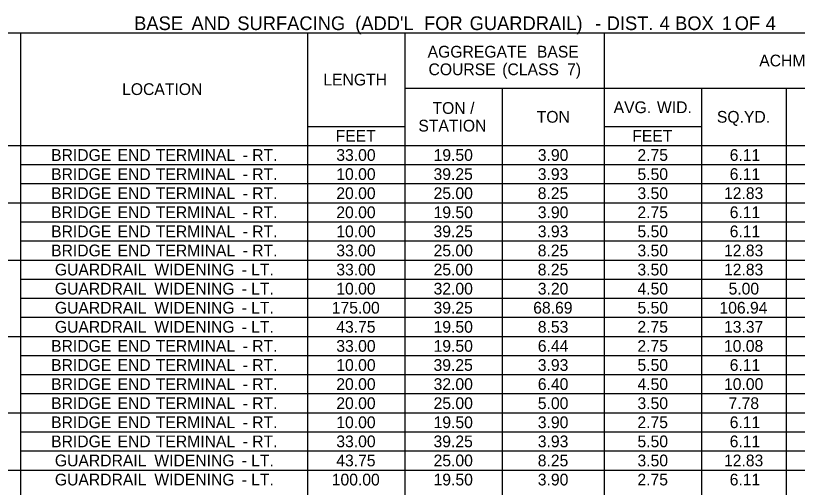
# Model space of a CAD drawing. Extents: x 540541 to 1930787, y -1948574 to 596640.
# Drawn here: x 556174.1 to 556573.6, y -1946479.8 to -1946238.9 of the extents above; entities that cross this region are included whole.
import ezdxf

# ---------------------------------------------------------------- set-up
doc = ezdxf.new("R2010")
doc.units = 0
doc.layers.add('Default', color=7, linetype='Continuous')

msp = doc.modelspace()

# ---------------------------------------------------------------- linework, layer by layer
at = {"layer": 'Default'}
for p, q in [((555955.32, -1946247.69), (556842.08, -1946247.69)), ((556176.64, -1946704.96), (556176.64, -1946247.69)), ((556323.38, -1946695.21), (556323.38, -1946247.69)), ((556373.11, -1946695.21), (556373.11, -1946247.69)), ((556474.99, -1946704.96), (556474.99, -1946247.69)), ((556373.11, -1946275.96), (556842.08, -1946275.96)), ((556422.83, -1946704.96), (556422.83, -1946275.96)), ((556524.72, -1946275.96), (556568.11, -1946275.96)), ((556524.72, -1946704.96), (556524.72, -1946275.96)), ((556568.11, -1946704.96), (556568.11, -1946275.96)), ((556323.38, -1946295.46), (556373.11, -1946295.46)), ((556373.11, -1946695.21), (556373.11, -1946295.46)), ((556474.99, -1946295.46), (556524.72, -1946295.46)), ((556474.99, -1946305.21), (556474.99, -1946295.46)), ((556524.72, -1946704.96), (556524.72, -1946295.46)), ((555955.32, -1946305.21), (556373.11, -1946305.21)), ((556373.11, -1946305.21), (556524.72, -1946305.21)), ((556422.83, -1946704.96), (556422.83, -1946305.21)), ((556524.72, -1946305.21), (556842.08, -1946305.21)), ((556568.11, -1946704.96), (556568.11, -1946305.21)), ((556176.64, -1946314.96), (556842.08, -1946314.96)), ((556323.38, -1946441.71), (556323.38, -1946314.96)), ((556176.64, -1946324.71), (556842.08, -1946324.71)), ((556126.92, -1946334.46), (556842.08, -1946334.46)), ((556176.64, -1946344.21), (556842.08, -1946344.21)), ((556176.64, -1946353.96), (556842.08, -1946353.96)), ((556126.92, -1946363.71), (556842.08, -1946363.71)), ((556176.64, -1946373.46), (556842.08, -1946373.46)), ((556176.64, -1946383.21), (556842.08, -1946383.21)), ((556176.64, -1946392.96), (556842.08, -1946392.96)), ((556126.92, -1946402.71), (556474.99, -1946402.71)), ((556422.83, -1946402.71), (556474.99, -1946402.71)), ((556474.99, -1946402.71), (556842.08, -1946402.71)), ((556176.64, -1946412.46), (556842.08, -1946412.46)), ((556176.64, -1946422.21), (556474.99, -1946422.21)), ((556422.83, -1946422.21), (556474.99, -1946422.21)), ((556474.99, -1946422.21), (556842.08, -1946422.21)), ((556176.64, -1946431.96), (556474.99, -1946431.96)), ((556422.83, -1946431.96), (556474.99, -1946431.96)), ((556474.99, -1946431.96), (556842.08, -1946431.96)), ((555955.32, -1946441.71), (556323.38, -1946441.71)), ((556126.92, -1946441.71), (556842.08, -1946441.71)), ((556176.64, -1946451.46), (556842.08, -1946451.46)), ((556323.38, -1946470.96), (556323.38, -1946451.46)), ((556176.64, -1946461.21), (556842.08, -1946461.21)), ((556126.92, -1946470.96), (556323.38, -1946470.96)), ((556176.64, -1946470.96), (556323.38, -1946470.96)), ((556323.38, -1946470.96), (556842.08, -1946470.96))]:
    msp.add_line(p, q, dxfattribs=at)

# ---------------------------------------------------------------- texts
for s, height, p in [('BASE', 7, (556234.63, -1946246.29)), (' AND', 7, (556261.33, -1946246.29)), (' SURFACING', 7, (556284.75, -1946246.29)), (" (ADD'L", 7, (556345.02, -1946246.29)), (' FOR', 7, (556380.19, -1946246.29)), (' GUARDRAIL)', 7, (556403.5, -1946246.29)), (' DIST.', 7, (556473.55, -1946246.29)), (' 4', 7, (556500.59, -1946246.29)), (' BOX', 7, (556508.52, -1946246.29)), (' 1', 7, (556532.42, -1946246.29)), (' OF', 7, (556538.99, -1946246.29)), (' 4', 7, (556554.84, -1946246.29)), (' -', 7, (556467.65, -1946246.29)), ('AGGREGATE', 6, (556384.64, -1946260.33)), (' BASE', 6, (556438.26, -1946260.33)), ('ACHM', 6, (556554.14, -1946264.83)), ('COURSE', 6, (556385.09, -1946269.33)), (' (CLASS', 6, (556420.54, -1946269.33)), (' 7)', 6, (556453.67, -1946269.33)), ('LENGTH', 6, (556331.33, -1946274.58)), ('LOCATION', 6, (556228.46, -1946279.45)), ('TON', 6, (556387.12, -1946289.09)), (' /', 6, (556404.15, -1946289.09)), ('AVG.', 6, (556479.71, -1946288.71)), (' WID.', 6, (556499.63, -1946288.71)), ('TON', 6, (556440.4, -1946293.59)), ('SQ.YD.', 6, (556532.49, -1946293.59)), ('STATION', 6, (556379.91, -1946298.09)), ('FEET', 6, (556337.61, -1946303.34)), ('FEET', 6, (556489.23, -1946303.34)), ('BRIDGE', 6, (556192.18, -1946313.09)), (' END', 6, (556223.88, -1946313.09)), (' TERMINAL', 6, (556243.46, -1946313.09)), (' RT.', 6, (556292.74, -1946313.09)), ('33.00', 6, (556337.96, -1946313.09)), ('19.50', 6, (556387.69, -1946313.09)), ('3.90', 6, (556440.96, -1946313.09)), ('2.75', 6, (556491.87, -1946313.09)), ('6.11', 6, (556539.03, -1946313.09)), (' -', 6, (556287.88, -1946313.09)), ('BRIDGE', 6, (556192.18, -1946322.84)), (' END', 6, (556223.88, -1946322.84)), (' TERMINAL', 6, (556243.46, -1946322.84)), (' RT.', 6, (556292.74, -1946322.84)), ('10.00', 6, (556337.96, -1946322.84)), ('39.25', 6, (556387.65, -1946322.84)), ('3.93', 6, (556440.95, -1946322.84)), ('5.50', 6, (556491.9, -1946322.84)), ('6.11', 6, (556539.03, -1946322.84)), (' -', 6, (556287.88, -1946322.84)), ('BRIDGE', 6, (556192.18, -1946332.59)), (' END', 6, (556223.88, -1946332.59)), (' TERMINAL', 6, (556243.46, -1946332.59)), (' RT.', 6, (556292.74, -1946332.59)), ('20.00', 6, (556337.96, -1946332.59)), ('25.00', 6, (556387.69, -1946332.59)), ('8.25', 6, (556440.92, -1946332.59)), ('3.50', 6, (556491.9, -1946332.59)), ('12.83', 6, (556536.12, -1946332.59)), (' -', 6, (556287.88, -1946332.59)), ('BRIDGE', 6, (556192.18, -1946342.34)), (' END', 6, (556223.88, -1946342.34)), (' TERMINAL', 6, (556243.46, -1946342.34)), (' RT.', 6, (556292.74, -1946342.34)), ('20.00', 6, (556337.96, -1946342.34)), ('19.50', 6, (556387.69, -1946342.34)), ('3.90', 6, (556440.96, -1946342.34)), ('2.75', 6, (556491.87, -1946342.34)), ('6.11', 6, (556539.03, -1946342.34)), (' -', 6, (556287.88, -1946342.34)), ('BRIDGE', 6, (556192.18, -1946352.09)), (' END', 6, (556223.88, -1946352.09)), (' TERMINAL', 6, (556243.46, -1946352.09)), (' -', 6, (556287.88, -1946352.09)), (' RT.', 6, (556292.74, -1946352.09)), ('10.00', 6, (556337.96, -1946352.09)), ('39.25', 6, (556387.65, -1946352.09)), ('3.93', 6, (556440.95, -1946352.09)), ('5.50', 6, (556491.9, -1946352.09)), ('6.11', 6, (556539.03, -1946352.09)), ('BRIDGE', 6, (556192.18, -1946361.84)), (' END', 6, (556223.88, -1946361.84)), (' TERMINAL', 6, (556243.46, -1946361.84)), (' RT.', 6, (556292.74, -1946361.84)), ('33.00', 6, (556337.96, -1946361.84)), ('25.00', 6, (556387.69, -1946361.84)), ('8.25', 6, (556440.92, -1946361.84)), ('3.50', 6, (556491.9, -1946361.84)), ('12.83', 6, (556536.12, -1946361.84)), (' -', 6, (556287.88, -1946361.84)), ('GUARDRAIL', 6, (556194.1, -1946371.59)), (' WIDENING', 6, (556242.72, -1946371.59)), ('33.00', 6, (556337.96, -1946371.59)), ('25.00', 6, (556387.69, -1946371.59)), ('8.25', 6, (556440.92, -1946371.59)), ('3.50', 6, (556491.9, -1946371.59)), ('12.83', 6, (556536.12, -1946371.59)), (' -', 6, (556287.36, -1946371.59)), (' LT.', 6, (556292.22, -1946371.59)), ('GUARDRAIL', 6, (556194.1, -1946381.34)), (' WIDENING', 6, (556242.72, -1946381.34)), (' LT.', 6, (556292.22, -1946381.34)), ('10.00', 6, (556337.96, -1946381.34)), ('32.00', 6, (556387.69, -1946381.34)), ('3.20', 6, (556440.96, -1946381.34)), ('4.50', 6, (556491.9, -1946381.34)), ('5.00', 6, (556538.46, -1946381.34)), (' -', 6, (556287.36, -1946381.34)), ('GUARDRAIL', 6, (556194.1, -1946391.09)), (' WIDENING', 6, (556242.72, -1946391.09)), (' LT.', 6, (556292.22, -1946391.09)), ('175.00', 6, (556335.63, -1946391.09)), ('39.25', 6, (556387.65, -1946391.09)), ('68.69', 6, (556438.61, -1946391.09)), ('5.50', 6, (556491.9, -1946391.09)), ('106.94', 6, (556533.8, -1946391.09)), (' -', 6, (556287.36, -1946391.09)), ('GUARDRAIL', 6, (556194.1, -1946400.84)), (' WIDENING', 6, (556242.72, -1946400.84)), (' LT.', 6, (556292.22, -1946400.84)), ('43.75', 6, (556337.93, -1946400.84)), ('19.50', 6, (556387.69, -1946400.84)), ('8.53', 6, (556440.95, -1946400.84)), ('2.75', 6, (556491.87, -1946400.84)), ('13.37', 6, (556536.12, -1946400.84)), (' -', 6, (556287.36, -1946400.84)), ('BRIDGE', 6, (556192.18, -1946410.59)), (' END', 6, (556223.88, -1946410.59)), (' TERMINAL', 6, (556243.46, -1946410.59)), (' RT.', 6, (556292.74, -1946410.59)), ('33.00', 6, (556337.96, -1946410.59)), ('19.50', 6, (556387.69, -1946410.59)), ('6.44', 6, (556440.96, -1946410.59)), ('2.75', 6, (556491.87, -1946410.59)), ('10.08', 6, (556536.11, -1946410.59)), (' -', 6, (556287.88, -1946410.59)), ('BRIDGE', 6, (556192.18, -1946420.34)), (' END', 6, (556223.88, -1946420.34)), (' TERMINAL', 6, (556243.46, -1946420.34)), (' RT.', 6, (556292.74, -1946420.34)), ('10.00', 6, (556337.96, -1946420.34)), ('39.25', 6, (556387.65, -1946420.34)), ('3.93', 6, (556440.95, -1946420.34)), ('5.50', 6, (556491.9, -1946420.34)), ('6.11', 6, (556539.03, -1946420.34)), (' -', 6, (556287.88, -1946420.34)), ('BRIDGE', 6, (556192.18, -1946430.09)), (' END', 6, (556223.88, -1946430.09)), (' TERMINAL', 6, (556243.46, -1946430.09)), (' RT.', 6, (556292.74, -1946430.09)), ('20.00', 6, (556337.96, -1946430.09)), ('32.00', 6, (556387.69, -1946430.09)), ('6.40', 6, (556440.96, -1946430.09)), ('4.50', 6, (556491.9, -1946430.09)), ('10.00', 6, (556536.13, -1946430.09)), (' -', 6, (556287.88, -1946430.09)), ('BRIDGE', 6, (556192.18, -1946439.84)), (' END', 6, (556223.88, -1946439.84)), (' TERMINAL', 6, (556243.46, -1946439.84)), (' -', 6, (556287.88, -1946439.84)), (' RT.', 6, (556292.74, -1946439.84)), ('20.00', 6, (556337.96, -1946439.84)), ('25.00', 6, (556387.69, -1946439.84)), ('5.00', 6, (556440.96, -1946439.84)), ('3.50', 6, (556491.9, -1946439.84)), ('7.78', 6, (556538.44, -1946439.84)), ('BRIDGE', 6, (556192.18, -1946449.59)), (' END', 6, (556223.88, -1946449.59)), (' TERMINAL', 6, (556243.46, -1946449.59)), (' RT.', 6, (556292.74, -1946449.59)), ('10.00', 6, (556337.96, -1946449.59)), ('19.50', 6, (556387.69, -1946449.59)), ('3.90', 6, (556440.96, -1946449.59)), ('2.75', 6, (556491.87, -1946449.59)), ('6.11', 6, (556539.03, -1946449.59)), (' -', 6, (556287.88, -1946449.59)), ('BRIDGE', 6, (556192.18, -1946459.34)), (' END', 6, (556223.88, -1946459.34)), (' TERMINAL', 6, (556243.46, -1946459.34)), (' RT.', 6, (556292.74, -1946459.34)), ('33.00', 6, (556337.96, -1946459.34)), ('39.25', 6, (556387.65, -1946459.34)), ('3.93', 6, (556440.95, -1946459.34)), ('5.50', 6, (556491.9, -1946459.34)), ('6.11', 6, (556539.03, -1946459.34)), (' -', 6, (556287.88, -1946459.34)), ('GUARDRAIL', 6, (556194.1, -1946469.09)), (' WIDENING', 6, (556242.72, -1946469.09)), (' LT.', 6, (556292.22, -1946469.09)), ('43.75', 6, (556337.93, -1946469.09)), ('25.00', 6, (556387.69, -1946469.09)), ('8.25', 6, (556440.92, -1946469.09)), ('3.50', 6, (556491.9, -1946469.09)), ('12.83', 6, (556536.12, -1946469.09)), (' -', 6, (556287.36, -1946469.09)), ('GUARDRAIL', 6, (556194.1, -1946478.84)), (' WIDENING', 6, (556242.72, -1946478.84)), (' LT.', 6, (556292.22, -1946478.84)), ('100.00', 6, (556335.63, -1946478.84)), ('19.50', 6, (556387.69, -1946478.84)), ('3.90', 6, (556440.96, -1946478.84)), ('2.75', 6, (556491.87, -1946478.84)), ('6.11', 6, (556539.03, -1946478.84)), (' -', 6, (556287.36, -1946478.84))]:
    msp.add_text(s, height=height, dxfattribs=at).set_placement(p)

doc.saveas('drawing.dxf')
